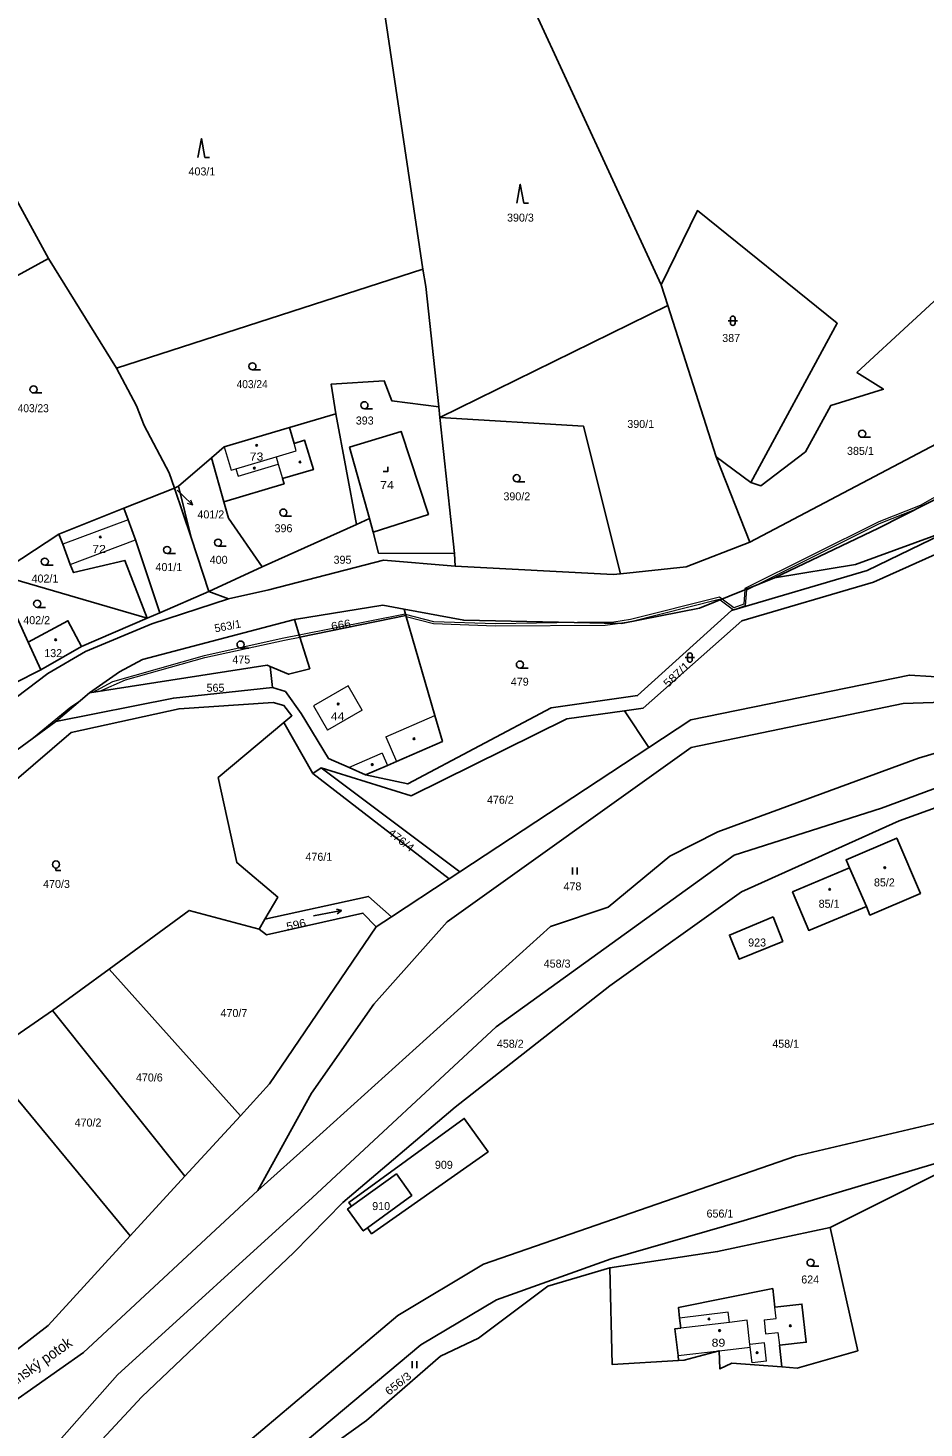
# Model space of a CAD drawing. Extents: x -754445 to -751443, y -1030748 to -1028224.
# Drawn here: x -753288.1 to -753097.8, y -1029073.5 to -1028776.1 of the extents above; entities that cross this region are included whole.
import ezdxf
from ezdxf.enums import TextEntityAlignment as Align

# ---------------------------------------------------------------- set-up
doc = ezdxf.new("R2010")
doc.units = 0
doc.header["$LTSCALE"] = 0.68
for name, color, linetype, lineweight in [('1', 7, 'Continuous', 25), ('13', 7, 'Continuous', 13), ('3', 7, 'Continuous', 25), ('4', 7, 'Continuous', 13), ('5', 7, 'Continuous', 25), ('7', 7, 'Continuous', 13)]:
    doc.layers.add(name, color=color, linetype=linetype, lineweight=lineweight)
doc.layers.add('2', color=7, linetype='Continuous')

msp = doc.modelspace()

# ---------------------------------------------------------------- linework, layer by layer
at = {"layer": '1'}
for p, q in [((-753312.31, -1028840.7), (-753283.77, -1028825.1)), ((-753152.22, -1028835.12), (-753200.62, -1028858.84)), ((-753222.7, -1028858.07), (-753232.59, -1028861)), ((-753222.7, -1028858.07), (-753218.32, -1028881.6)), ((-753200.62, -1028858.84), (-753197.5, -1028887.73)), ((-753090.47, -1028862.01), (-753134.8, -1028885.38)), ((-753267.75, -1028878.15), (-753256.99, -1028873.88)), ((-753256.99, -1028873.88), (-753256.11, -1028873.47)), ((-753253.43, -1028884.37), (-753256.99, -1028873.88)), ((-753267.75, -1028878.15), (-753281.53, -1028883.63)), ((-753218.32, -1028881.6), (-753215.53, -1028880.35)), ((-753215.53, -1028880.35), (-753214.8, -1028883.22)), ((-753197.5, -1028887.73), (-753197.37, -1028890.48)), ((-753249.7, -1028895.85), (-753260.09, -1028900.33)), ((-753208.22, -1028899.58), (-753207.83, -1028900.94)), ((-753276.76, -1028907.53), (-753262.81, -1028901.51)), ((-753230.36, -1028905.5), (-753231.52, -1028901.77)), ((-753207.83, -1028900.94), (-753230.36, -1028905.5)), ((-753285.35, -1028912.45), (-753276.76, -1028907.53)), ((-753236.68, -1028911.74), (-753236.18, -1028916.23)), ((-753282.22, -1028923.45), (-753275.02, -1028917.34)), ((-753156.24, -1028928.95), (-753161.4, -1028921.14)), ((-753227.62, -1028934.47), (-753233.79, -1028923.65)), ((-753225.84, -1028933.3), (-753227.62, -1028934.47)), ((-753198.65, -1028956.85), (-753227.62, -1028934.47)), ((-753198.65, -1028956.85), (-753196.4, -1028955.37)), ((-753110, -1028962.69), (-753113.58, -1028954.54)), ((-753239, -1028967.55), (-753237.78, -1028965.43)), ((-753210.91, -1028964.91), (-753214.16, -1028967.05)), ((-753282.89, -1028984.8), (-753270.89, -1028976.01)), ((-753243, -1029007.16), (-753270.89, -1028976.01)), ((-753254.77, -1029020), (-753282.89, -1028984.8)), ((-753254.77, -1029020), (-753243, -1029007.16)), ((-753266.4, -1029032.68), (-753254.77, -1029020))]:
    msp.add_line(p, q, dxfattribs=at)
for points in [[(-753171.36, -1028757.48), (-753175.6, -1028762.63), (-753183.17, -1028765.18), (-753181.84, -1028769.43), (-753153.59, -1028830.68)], [(-753203.96, -1028770.33), (-753212.4, -1028772.78), (-753204.22, -1028827.36)], [(-753307.71, -1028780.5), (-753297.08, -1028800.82), (-753283.77, -1028825.1)], [(-753153.59, -1028830.68), (-753145.91, -1028814.92), (-753116.22, -1028838.86), (-753134.58, -1028872.67)], [(-753134.58, -1028872.67), (-753132.43, -1028873.36), (-753122.96, -1028866.17), (-753117.58, -1028856.31), (-753106.38, -1028852.88), (-753112.03, -1028849.29), (-753088.4, -1028827.5), (-753073.04, -1028822.98), (-753068.26, -1028822.65)], [(-753283.77, -1028825.1), (-753269.27, -1028848.36), (-753204.22, -1028827.36)], [(-753204.22, -1028827.36), (-753203.62, -1028831.02), (-753200.86, -1028856.64), (-753200.62, -1028858.84)], [(-753153.59, -1028830.68), (-753152.22, -1028835.12), (-753141.9, -1028867.24), (-753134.58, -1028872.67)], [(-753256.99, -1028873.88), (-753258.14, -1028870.64), (-753263.44, -1028860.6), (-753265.06, -1028856.39), (-753269.27, -1028848.36)], [(-753200.86, -1028856.64), (-753210.83, -1028855.33), (-753212.46, -1028851.05), (-753223.72, -1028851.82), (-753222.7, -1028858.07)], [(-753200.62, -1028858.84), (-753170.13, -1028860.7), (-753162.26, -1028892.04)], [(-753232.59, -1028861), (-753246.41, -1028865.1), (-753249.13, -1028867.45), (-753246.53, -1028876.75)], [(-753246.53, -1028876.75), (-753233.7, -1028872.94), (-753234.03, -1028871.86), (-753227.49, -1028869.92), (-753229.34, -1028863.69), (-753231.59, -1028864.36), (-753232.59, -1028861)], [(-753214.8, -1028883.22), (-753203.06, -1028879.46), (-753208.85, -1028861.83), (-753219.79, -1028865.14), (-753215.53, -1028880.35)], [(-752999.76, -1028861.33), (-753031.31, -1028867.54), (-753047.75, -1028876.58), (-753066.39, -1028874.93), (-753108.51, -1028893.85), (-753136.48, -1028902.04), (-753157.46, -1028920.58), (-753161.4, -1028921.14)], [(-753156.24, -1028928.95), (-753147.31, -1028923.08), (-753100.88, -1028913.59), (-753087.08, -1028914.44), (-753051.19, -1028900.21), (-753031.73, -1028894.6), (-753019.72, -1028889.12), (-753004.25, -1028876.84), (-752998.07, -1028868.64), (-752999.76, -1028861.33)], [(-753249.13, -1028867.45), (-753256.11, -1028873.47), (-753253.43, -1028884.37), (-753249.7, -1028895.85)], [(-753162.26, -1028892.04), (-753148.27, -1028890.62), (-753134.8, -1028885.38), (-753141.9, -1028867.24)], [(-753073.97, -1028865.83), (-753081.42, -1028869.21), (-753107.45, -1028882.38), (-753129.56, -1028892.89)], [(-753246.53, -1028876.75), (-753245.54, -1028880.28), (-753238.37, -1028890.57)], [(-753260.09, -1028900.33), (-753265.24, -1028884.85), (-753266.84, -1028880.58), (-753267.75, -1028878.15)], [(-753218.32, -1028881.6), (-753238.37, -1028890.57), (-753249.7, -1028895.85), (-753245.48, -1028897.41)], [(-753216.41, -1028934.77), (-753207.44, -1028936.69), (-753177, -1028920.55), (-753158.6, -1028917.93), (-753138.66, -1028899.83), (-753109.83, -1028891.4), (-753091.6, -1028882.51)], [(-753091.6, -1028882.51), (-753112.3, -1028890.06), (-753129.56, -1028892.89)], [(-753281.53, -1028883.63), (-753294.67, -1028892.21), (-753262.81, -1028901.51)], [(-753281.53, -1028883.63), (-753280.72, -1028885.79), (-753279.12, -1028890.06), (-753278.47, -1028891.8), (-753267.51, -1028889.23), (-753262.81, -1028901.51), (-753260.09, -1028900.33)], [(-753214.8, -1028883.22), (-753213.65, -1028887.7), (-753197.5, -1028887.73)], [(-753288.04, -1028906.61), (-753294.67, -1028892.21), (-753297.57, -1028885.92)], [(-753245.48, -1028897.41), (-753236.96, -1028895.44), (-753212.59, -1028889.18), (-753197.37, -1028890.48)], [(-753197.37, -1028890.48), (-753163.79, -1028892.2), (-753162.26, -1028892.04)], [(-753129.56, -1028892.89), (-753145.44, -1028899.38), (-753162.04, -1028902.64), (-753195.53, -1028901.94), (-753208.22, -1028899.58)], [(-753245.48, -1028897.41), (-753261.79, -1028902.68), (-753275.92, -1028908.54), (-753283.86, -1028913.22), (-753307.94, -1028931.4)], [(-753231.52, -1028901.77), (-753212.71, -1028898.74), (-753208.22, -1028899.58)], [(-753276.76, -1028907.53), (-753279.64, -1028902.05), (-753288.04, -1028906.61)], [(-753231.52, -1028901.77), (-753263.75, -1028910.25), (-753268.64, -1028912.92), (-753275.02, -1028917.34)], [(-753216.41, -1028934.77), (-753211.77, -1028932.75), (-753209.83, -1028931.91), (-753200.06, -1028927.66), (-753201.66, -1028922.14), (-753207.83, -1028900.94)], [(-753296.61, -1028918.16), (-753285.35, -1028912.45), (-753288.04, -1028906.61)], [(-753230.36, -1028905.5), (-753228.26, -1028912.24), (-753232.74, -1028913.39), (-753236.68, -1028911.74)], [(-753061.57, -1028909.5), (-753085.23, -1028919.06), (-753102.18, -1028919.63), (-753147.2, -1028928.97), (-753199.09, -1028965.99), (-753214.67, -1028983.44), (-753227.91, -1029002.35), (-753239.27, -1029023.03)], [(-753275.02, -1028917.34), (-753237.33, -1028911.47), (-753236.68, -1028911.74)], [(-753042.14, -1028917.9), (-753106.78, -1028941.85), (-753138.13, -1028951.79), (-753188.66, -1028988.29), (-753227.66, -1029024.5), (-753269.09, -1029062.17), (-753299.36, -1029096.33)], [(-753282.22, -1028923.45), (-753257.2, -1028918.47), (-753236.18, -1028916.23)], [(-753236.18, -1028916.23), (-753233.41, -1028917.09), (-753230.06, -1028921.73), (-753224.27, -1028931.31), (-753219.91, -1028933.23), (-753216.41, -1028934.77)], [(-753233.79, -1028923.65), (-753232.06, -1028922.2), (-753233.74, -1028920.02), (-753236.01, -1028919.42), (-753256.01, -1028920.74), (-753278.94, -1028925.76), (-753298.71, -1028942.67)], [(-753161.4, -1028921.14), (-753173.64, -1028922.89), (-753206.69, -1028939.21), (-753225.84, -1028933.3), (-753196.4, -1028955.37), (-753156.24, -1028928.95)], [(-753300.94, -1028940.42), (-753291.49, -1028930.23), (-753282.22, -1028923.45)], [(-753237.78, -1028965.43), (-753235.05, -1028960.72), (-753243.75, -1028953.38), (-753247.71, -1028935.35), (-753233.79, -1028923.65)], [(-753072.54, -1028923.37), (-753098.97, -1028931.22), (-753141.59, -1028946.89), (-753151.77, -1028952.05), (-753164.86, -1028962.85), (-753177.15, -1028966.98), (-753227.57, -1029012.56), (-753239.27, -1029023.03)], [(-753049.6, -1028925.31), (-753103.08, -1028944.56), (-753136.56, -1028959.62), (-753164.51, -1028979.55), (-753197.36, -1029005.36), (-753221.21, -1029025.61), (-753231.65, -1029036.2), (-753263.95, -1029066.84), (-753289.3, -1029094.11), (-753299.36, -1029096.33), (-753321.63, -1029103.19)], [(-753110, -1028962.69), (-753109.28, -1028964.56), (-753098.52, -1028959.94), (-753103.57, -1028948.18), (-753114.33, -1028952.8), (-753113.58, -1028954.54)], [(-753237.78, -1028965.43), (-753215.74, -1028960.59), (-753210.91, -1028964.91), (-753198.65, -1028956.85)], [(-753113.58, -1028954.54), (-753125.68, -1028959.61), (-753122.24, -1028967.82), (-753110, -1028962.69)], [(-753270.89, -1028976.01), (-753253.9, -1028963.56), (-753239, -1028967.55)], [(-753214.16, -1028967.05), (-753216.96, -1028964.12), (-753237.41, -1028968.74), (-753239, -1028967.55)], [(-753243, -1029007.16), (-753236.82, -1029000.42), (-753214.16, -1028967.05)], [(-753282.89, -1028984.8), (-753297.62, -1028994.95), (-753266.4, -1029032.68)], [(-753117.68, -1029030.87), (-753083.51, -1029013.75), (-753049.19, -1028999.5), (-753050.62, -1028996.17)], [(-753219.36, -1029026.37), (-753219.93, -1029025.56), (-753195.42, -1029007.73), (-753190.39, -1029014.8), (-753215.11, -1029032.21), (-753215.99, -1029030.96)], [(-753272.08, -1029104.35), (-753257.32, -1029089.93), (-753209.56, -1029049.56), (-753191.33, -1029038.68), (-753125.1, -1029015.75), (-753094.96, -1029008.68)], [(-753258.72, -1029106.42), (-753258.82, -1029103.04), (-753254.14, -1029097.3), (-753204.68, -1029055.84), (-753188.6, -1029046.26), (-753164.24, -1029037.55), (-753135.98, -1029029.42), (-753083.51, -1029013.75)], [(-753219.36, -1029026.37), (-753209.84, -1029019.52), (-753206.58, -1029024.09), (-753215.99, -1029030.96)], [(-753239.27, -1029023.03), (-753276.34, -1029057.44), (-753301.53, -1029075.12), (-753321.63, -1029103.19)], [(-753215.99, -1029030.96), (-753216.9, -1029031.63), (-753220.22, -1029026.99), (-753219.36, -1029026.37)], [(-753117.68, -1029030.87), (-753141.64, -1029036.01), (-753164.52, -1029039.45), (-753164.03, -1029059.98), (-753149.91, -1029059.12)], [(-753127.97, -1029060.52), (-753124.73, -1029060.76), (-753111.85, -1029057.06), (-753117.68, -1029030.87)], [(-753306.72, -1029067.62), (-753304.1, -1029067.37), (-753283.84, -1029051.7), (-753266.4, -1029032.68)], [(-753231.51, -1029082.83), (-753216.18, -1029071.9), (-753200.47, -1029058.23), (-753192.42, -1029054.41), (-753177.68, -1029043.39), (-753164.52, -1029039.45)], [(-753127.97, -1029060.52), (-753128.5, -1029055.92), (-753122.78, -1029055.26), (-753123.72, -1029047.18), (-753129.44, -1029047.85), (-753129.91, -1029043.88), (-753149.96, -1029047.92), (-753149.7, -1029050.12), (-753149.45, -1029052.25), (-753150.7, -1029052.4), (-753150.03, -1029058.11), (-753149.91, -1029059.12)], [(-753149.91, -1029059.12), (-753148.73, -1029059.05), (-753141.3, -1029057.09), (-753141.13, -1029060.92), (-753138.63, -1029059.73), (-753127.97, -1029060.52)]]:
    msp.add_lwpolyline(points, dxfattribs=at)
msp.add_lwpolyline([(-753129.85, -1028964.94), (-753127.77, -1028970.14), (-753137.02, -1028973.93), (-753139.12, -1028968.8)], close=True, dxfattribs=at)
at = {"layer": '13'}
msp.add_lwpolyline([(-753082.4, -1028868.35), (-753098.62, -1028877.58), (-753107.4, -1028881.05), (-753135.8, -1028895.22), (-753135.82, -1028895.45), (-753133.27, -1028894.4), (-753107.24, -1028881.41), (-753099.5, -1028878.36), (-753096.13, -1028876.65)], dxfattribs=at)
for points in [[(-753138.16, -1028899.27), (-753140.67, -1028897.43), (-753141.1, -1028897.61), (-753138.22, -1028899.71), (-753135.68, -1028898.8), (-753135.42, -1028895.48), (-753133.27, -1028894.4), (-753135.82, -1028895.45), (-753136.06, -1028898.52)], [(-753160.11, -1028901.8), (-753163.66, -1028902.33), (-753171.41, -1028902.44), (-753162.89, -1028902.62), (-753160.03, -1028902.2), (-753141.32, -1028897.45), (-753141.1, -1028897.61), (-753140.67, -1028897.43), (-753141.24, -1028897.01)], [(-753208.02, -1028900.65), (-753230.49, -1028905.1), (-753230.36, -1028905.5), (-753207.83, -1028900.94), (-753207.9, -1028900.68)], [(-753188.77, -1028902.7), (-753201.88, -1028902.24), (-753207.9, -1028900.68), (-753207.78, -1028901.12), (-753201.94, -1028902.64), (-753188.77, -1028903.1), (-753165.52, -1028903.01), (-753162.89, -1028902.62), (-753171.41, -1028902.44)], [(-753250.66, -1028909.47), (-753270.15, -1028915.02), (-753273.68, -1028916.91), (-753274.13, -1028917.2), (-753272.88, -1028917.01), (-753267.37, -1028914.6), (-753250.56, -1028909.85), (-753233.65, -1028906.14), (-753230.36, -1028905.5), (-753230.49, -1028905.1), (-753233.73, -1028905.74)], [(-753286.95, -1028926.91), (-753282.22, -1028923.45), (-753277.28, -1028919.26), (-753279.03, -1028920.4)]]:
    msp.add_lwpolyline(points, close=True, dxfattribs=at)
at = {"layer": '3'}
for p, q in [((-753250.52, -1028803.62), (-753249.524, -1028803.62)), ((-753182.8, -1028813.33), (-753181.804, -1028813.33)), ((-753138.891, -1028837.821), (-753138.891, -1028838.822)), ((-753137.889, -1028838.822), (-753137.889, -1028837.821)), ((-753139.391, -1028838.321), (-753137.389, -1028838.321)), ((-753240.433, -1028848.75), (-753238.683, -1028848.75)), ((-753286.933, -1028853.66), (-753285.183, -1028853.66)), ((-753216.643, -1028857.01), (-753214.893, -1028857.01)), ((-753110.913, -1028863.08), (-753109.163, -1028863.08)), ((-753184.293, -1028872.51), (-753182.543, -1028872.51)), ((-753233.873, -1028879.81), (-753232.123, -1028879.81)), ((-753258.553, -1028887.75), (-753256.803, -1028887.75)), ((-753247.733, -1028886.19), (-753245.983, -1028886.19)), ((-753284.533, -1028890.23), (-753282.783, -1028890.23)), ((-753286.153, -1028899.19), (-753284.403, -1028899.19)), ((-753242.953, -1028907.84), (-753241.203, -1028907.84)), ((-753148.011, -1028909.361), (-753148.011, -1028910.362)), ((-753147.009, -1028910.362), (-753147.009, -1028909.361)), ((-753183.613, -1028912.09), (-753181.863, -1028912.09)), ((-753148.511, -1028909.861), (-753146.509, -1028909.861)), ((-753172.461, -1028955.91), (-753172.461, -1028954.41)), ((-753171.46, -1028955.91), (-753171.46, -1028954.41)), ((-753221.537, -1028963.573), (-753222.4, -1028964.251)), ((-753121.873, -1029039.1), (-753120.123, -1029039.1)), ((-753206.491, -1029060.8), (-753206.491, -1029059.3)), ((-753205.49, -1029060.8), (-753205.49, -1029059.3))]:
    msp.add_line(p, q, dxfattribs=at)
for points in [[(-753250.52, -1028803.62), (-753251.27, -1028799.62), (-753252.02, -1028803.62)], [(-753182.8, -1028813.33), (-753183.55, -1028809.33), (-753184.3, -1028813.33)], [(-753212.691, -1028870.37), (-753211.69, -1028870.37), (-753211.69, -1028869.37)], [(-753282.16, -1028954.552), (-753282.16, -1028955.05), (-753281.159, -1028955.05)], [(-753227.426, -1028964.718), (-753221.537, -1028963.573), (-753222.592, -1028963.267)]]:
    msp.add_lwpolyline(points, dxfattribs=at)
for centre in [(-753240.4329, -1028847.9998), (-753286.9329, -1028852.9098), (-753216.6429, -1028856.2598), (-753110.9129, -1028862.3298), (-753184.2929, -1028871.7598), (-753233.8729, -1028879.0598), (-753247.7329, -1028885.4398), (-753284.5329, -1028889.4798), (-753258.5529, -1028886.9998), (-753286.1529, -1028898.4398), (-753242.9529, -1028907.0898), (-753183.6129, -1028911.3398), (-753282.1593, -1028953.8009), (-753121.8729, -1029038.3498)]:
    msp.add_circle(centre, 0.75, dxfattribs=at)
for centre, start, end in [((-753138.39, -1028837.8209), 0, 180), ((-753138.39, -1028838.8209), 180, 359.98789), ((-753147.51, -1028909.3609), 0, 180), ((-753147.51, -1028910.3609), 180, 359.98789)]:
    msp.add_arc(centre, 0.5, start, end, dxfattribs=at)
at = {"layer": '4'}
for p, q in [((-753231.12, -1028865.94), (-753231.59, -1028864.36)), ((-753246.41, -1028865.1), (-753244.94, -1028870.04)), ((-753243.94, -1028869.74), (-753235.41, -1028867.21)), ((-753235.41, -1028867.21), (-753231.12, -1028865.94)), ((-753235.41, -1028867.21), (-753234.94, -1028868.79)), ((-753244.94, -1028870.04), (-753243.94, -1028869.74)), ((-753243.94, -1028869.74), (-753243.47, -1028871.32)), ((-753243.47, -1028871.32), (-753234.94, -1028868.79)), ((-753234.94, -1028868.79), (-753234.03, -1028871.86)), ((-753266.84, -1028880.58), (-753280.72, -1028885.79)), ((-753279.12, -1028890.06), (-753265.24, -1028884.85)), ((-753220.08, -1028915.87), (-753227.46, -1028920.09)), ((-753217.11, -1028921.06), (-753220.08, -1028915.87)), ((-753227.46, -1028920.09), (-753224.49, -1028925.28)), ((-753217.11, -1028921.06), (-753224.49, -1028925.28)), ((-753212.11, -1028926.68), (-753201.66, -1028922.14)), ((-753212.11, -1028926.68), (-753209.83, -1028931.91)), ((-753212.89, -1028930.17), (-753219.91, -1028933.23)), ((-753212.89, -1028930.17), (-753211.77, -1028932.75)), ((-753139.36, -1029048.91), (-753149.7, -1029050.12)), ((-753139.11, -1029051.05), (-753139.36, -1029048.91)), ((-753129.16, -1029050.21), (-753129.44, -1029047.85)), ((-753139.11, -1029051.05), (-753149.45, -1029052.25)), ((-753135.34, -1029050.61), (-753139.11, -1029051.05)), ((-753131.75, -1029050.51), (-753129.16, -1029050.21)), ((-753131.75, -1029050.51), (-753131.41, -1029053.47)), ((-753131.41, -1029053.47), (-753128.82, -1029053.17)), ((-753128.82, -1029053.17), (-753128.5, -1029055.92)), ((-753150.03, -1029058.11), (-753141.3, -1029057.09)), ((-753141.3, -1029057.09), (-753134.68, -1029056.32)), ((-753134.68, -1029056.32), (-753134.74, -1029055.73)), ((-753134.29, -1029059.62), (-753134.68, -1029056.32)), ((-753131.2, -1029059.3), (-753131.65, -1029055.37)), ((-753131.2, -1029059.3), (-753134.29, -1029059.62))]:
    msp.add_line(p, q, dxfattribs=at)
msp.add_lwpolyline([(-753131.65, -1029055.37), (-753134.74, -1029055.73), (-753135.34, -1029050.61)], dxfattribs=at)
at = {"layer": '5'}
for centre in [(-753239.5268, -1028864.7892), (-753240.0268, -1028869.6292), (-753230.3268, -1028868.3092), (-753272.7468, -1028884.2392), (-753282.2168, -1028906.0792), (-753222.2068, -1028919.7192), (-753206.1168, -1028927.1092), (-753214.9868, -1028932.5692), (-753106.1068, -1028954.4792), (-753117.7968, -1028959.0692), (-753143.4468, -1029050.3192), (-753126.1668, -1029051.7692), (-753141.2068, -1029052.7792), (-753133.2168, -1029057.4692)]:
    msp.add_circle(centre, 0.175, dxfattribs=at)
at = {"layer": '7'}
msp.add_line((-753253.121, -1028877.485), (-753253.494, -1028876.429), dxfattribs=at)
msp.add_lwpolyline([(-753256.39, -1028874.33), (-753255.28, -1028875.4), (-753253.121, -1028877.485), (-753254.19, -1028877.149)], dxfattribs=at)

# ---------------------------------------------------------------- texts
at = {"layer": '2'}
for s, p in [('403/1', (-753251.16, -1028807.46)), ('390/3', (-753183.5, -1028817.27)), ('387', (-753138.739, -1028842.83)), ('393', (-753216.579, -1028860.36)), ('390/1', (-753157.95, -1028861.09)), ('385/1', (-753111.28, -1028866.81)), ('390/2', (-753184.27, -1028876.47)), ('396', (-753233.829, -1028883.24)), ('400', (-753247.599, -1028889.94)), ('395', (-753221.299, -1028889.93)), ('401/1', (-753258.18, -1028891.49)), ('402/1', (-753284.5, -1028893.92)), ('402/2', (-753286.26, -1028902.77)), ('132', (-753282.749, -1028909.76)), ('475', (-753242.799, -1028911.12)), ('565', (-753248.279, -1028917.12)), ('479', (-753183.639, -1028915.83)), ('476/2', (-753187.76, -1028940.9)), ('476/1', (-753226.32, -1028953.02)), ('470/3', (-753282.05, -1028958.79)), ('85/2', (-753106.19, -1028958.46)), ('478', (-753172.449, -1028959.29)), ('85/1', (-753117.94, -1028962.99)), ('923', (-753133.229, -1028971.22)), ('458/3', (-753175.71, -1028975.7)), ('470/7', (-753244.36, -1028986.2)), ('458/2', (-753185.66, -1028992.72)), ('458/1', (-753127.16, -1028992.72)), ('470/6', (-753262.33, -1028999.89)), ('470/2', (-753275.35, -1029009.46)), ('909', (-753199.769, -1029018.43)), ('910', (-753213.089, -1029027.2)), ('656/1', (-753141.12, -1029028.79)), ('624', (-753121.949, -1029042.79))]:
    msp.add_text(s, height=1.7, dxfattribs=at).set_placement(p, align=Align.CENTER)
for s, width, p in [('403/24', 0.95, (-753240.489, -1028852.64)), ('403/23', 0.95, (-753286.989, -1028857.75)), ('73', 1.15, (-753239.56, -1028868.01)), ('74', 1.15, (-753211.84, -1028874.08)), ('72', 1.15, (-753273, -1028887.64)), ('44', 1.15, (-753222.34, -1028923.18)), ('89', 1.15, (-753141.44, -1029056.22))]:
    msp.add_text(s, height=1.7, dxfattribs=dict(at, width=width)).set_placement(p, align=Align.CENTER)
msp.add_text('401/2', height=1.7, dxfattribs=at).set_placement((-753252.11, -1028880.303))
msp.add_text('563/1', height=1.7, rotation=11, dxfattribs=at).set_placement((-753245.5292, -1028903.9827), align=Align.CENTER)
for s, rotation, width, p in [('666', 10, 1.1, (-753221.4841, -1028903.7398)), ('587/1', 43, 1.15, (-753149.7832, -1028914.0812)), ('476/4', 322, 1.1, (-753209.3633, -1028949.2923)), ('596', 13, 1.1, (-753230.9617, -1028967.3984)), ('656/3', 38, 1.1, (-753208.9673, -1029064.7067))]:
    msp.add_text(s, height=1.7, rotation=rotation, dxfattribs=dict(at, width=width)).set_placement(p, align=Align.CENTER)
at = {"layer": '7', "width": 0.95}
msp.add_text('Zákolanský potok', height=2.3, rotation=35, dxfattribs=at).set_placement((-753287.8006, -1029062.412), align=Align.CENTER)

doc.saveas('drawing.dxf')
